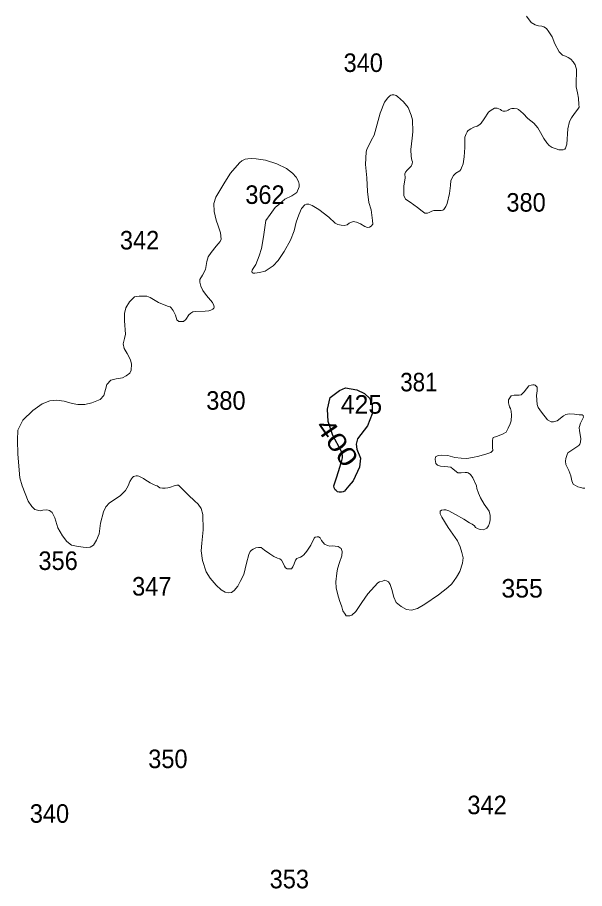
# Model space of a CAD drawing. Extents: x 445.4 to 500, y 8728.7 to 8784.
# Drawn here: x 453.47 to 458.36, y 8752.84 to 8760.36 of the extents above; entities that cross this region are included whole.
import ezdxf
from ezdxf.enums import TextEntityAlignment as Align

# ---------------------------------------------------------------- set-up
doc = ezdxf.new("R2010")
doc.units = 0
doc.header["$LTSCALE"] = 0.064
doc.layers.add('1', color=7, linetype='Continuous', lineweight=25)
doc.layers.add('2', color=7, linetype='Continuous', lineweight=13)
doc.layers.add('21', color=7, linetype='Continuous')
doc.layers.add('61', color=7, linetype='Continuous')

msp = doc.modelspace()

# ---------------------------------------------------------------- linework, layer by layer
at = {"layer": '1'}
msp.add_lwpolyline([(456.3024, 8756.2833), (456.2935, 8756.2721), (456.2812, 8756.2654), (456.2656, 8756.2632), (456.2478, 8756.2643), (456.2333, 8756.2677), (456.2221, 8756.2766), (456.2132, 8756.2844), (456.2031, 8756.3), (456.202, 8756.3168), (456.2269, 8756.3972), (456.2528, 8756.4782), (456.269, 8756.5365), (456.2755, 8756.5591), (456.2755, 8756.5786), (456.2626, 8756.6207), (456.1912, 8756.7534), (456.1523, 8756.8732), (456.1458, 8756.9801), (456.1685, 8757.0805), (456.2496, 8757.142), (456.3015, 8757.1647), (456.3988, 8757.1453), (456.4636, 8757.1161), (456.5123, 8757.0708), (456.5317, 8757.0157), (456.5317, 8756.938), (456.4896, 8756.8344), (456.4052, 8756.7243), (456.3923, 8756.6789), (456.3988, 8756.6336), (456.4312, 8756.5559), (456.4215, 8756.4782), (456.3663, 8756.3616), (456.3292, 8756.3168)], close=True, dxfattribs=at)
at = {"layer": '2'}
for points in [[(457.8603, 8760.3698), (457.9029, 8760.3157), (457.9349, 8760.2953), (457.966, 8760.2864), (457.9944, 8760.282), (458.0104, 8760.2776), (458.0326, 8760.2643), (458.0539, 8760.2341), (458.0832, 8760.1915), (458.1066, 8760.1306), (458.143, 8760.0605), (458.1723, 8760.0321), (458.1989, 8760.0233), (458.2194, 8760.0126), (458.2442, 8759.9975), (458.2638, 8759.9754), (458.2798, 8759.9487), (458.2878, 8759.931), (458.2931, 8759.9115), (458.294, 8759.8656), (458.2904, 8759.8213), (458.2887, 8759.7885), (458.2904, 8759.7601), (458.302, 8759.7069), (458.3108, 8759.661), (458.3135, 8759.6078), (458.3144, 8759.5839), (458.3055, 8759.567), (458.2744, 8759.5289), (458.2487, 8759.4934), (458.2336, 8759.4597), (458.218, 8759.3988), (458.2079, 8759.2659), (458.197, 8759.2319), (458.1909, 8759.2221), (458.1763, 8759.2161), (458.1587, 8759.2167), (458.1398, 8759.2179), (458.1185, 8759.224), (458.0833, 8759.2367), (458.0583, 8759.2537), (458.037, 8759.2774), (458.0109, 8759.3157), (457.9828, 8759.3665), (457.9585, 8759.4054), (457.9256, 8759.4479), (457.8743, 8759.486), (457.8335, 8759.5309), (457.794, 8759.5631), (457.78, 8759.571), (457.7551, 8759.574), (457.735, 8759.5722), (457.7234, 8759.5698), (457.7119, 8759.5655), (457.7046, 8759.5601), (457.693, 8759.5522), (457.6784, 8759.5491), (457.6608, 8759.5497), (457.6516, 8759.5528), (457.6456, 8759.5564), (457.6364, 8759.5631), (457.6243, 8759.5698), (457.6091, 8759.5746), (457.5945, 8759.5771), (457.5847, 8759.5753), (457.558, 8759.5589), (457.5352, 8759.5403), (457.4969, 8759.4838), (457.4713, 8759.4461), (457.4628, 8759.4376), (457.4506, 8759.4291), (457.4372, 8759.42), (457.4079, 8759.4111), (457.3817, 8759.3984), (457.3665, 8759.3892), (457.3568, 8759.3807), (457.3495, 8759.371), (457.3404, 8759.3552), (457.3349, 8759.34), (457.3294, 8759.3249), (457.33, 8759.2357), (457.3245, 8759.1549), (457.3142, 8759.0972), (457.3013, 8759.0622), (457.2952, 8759.0465), (457.2854, 8759.0355), (457.2526, 8759.0143), (457.2325, 8758.996), (457.21, 8758.9511), (457.2063, 8758.9093)], [(457.2063, 8758.9093), (457.1966, 8758.8394), (457.1784, 8758.7532), (457.1658, 8758.728), (457.1555, 8758.7104), (457.1476, 8758.7013), (457.1391, 8758.697), (457.1269, 8758.6934), (457.0935, 8758.694), (457.0624, 8758.6934), (457.0466, 8758.6873), (457.0235, 8758.6746), (457.0083, 8758.6697), (456.9961, 8758.6697), (456.9864, 8758.6709), (456.9627, 8758.6873), (456.9219, 8758.7183), (456.8574, 8758.7651), (456.8172, 8758.7923), (456.8038, 8758.8233), (456.8044, 8758.8494), (456.8038, 8758.9041), (456.8154, 8758.9762), (456.8136, 8759.009), (456.8184, 8759.0248), (456.8337, 8759.0418), (456.8665, 8759.0746), (456.8768, 8759.0965), (456.8787, 8759.1123), (456.8744, 8759.1281), (456.8683, 8759.1577), (456.8647, 8759.2185), (456.875, 8759.3163), (456.8829, 8759.3707), (456.8787, 8759.4758), (456.8682, 8759.517), (456.8402, 8759.582), (456.8007, 8759.6312), (456.7502, 8759.6774), (456.7393, 8759.6853), (456.7295, 8759.6895), (456.7168, 8759.6907), (456.7028, 8759.6901), (456.693, 8759.6883), (456.6833, 8759.681), (456.665, 8759.6658), (456.6381, 8759.6268), (456.6002, 8759.533), (456.5472, 8759.3428), (456.5225, 8759.2967), (456.4852, 8759.2189), (456.4779, 8759.198), (456.4737, 8759.089), (456.4852, 8758.9741), (456.4915, 8758.8577), (456.503, 8758.7624), (456.5227, 8758.699), (456.5343, 8758.6079), (456.536, 8758.5767), (456.5217, 8758.5576), (456.507, 8758.5492), (456.4902, 8758.5471), (456.4692, 8758.5544), (456.4304, 8758.5796), (456.3958, 8758.5932), (456.3685, 8758.5974), (456.3341, 8758.5833), (456.316, 8758.5701), (456.2887, 8758.5639), (456.2646, 8758.566), (456.2342, 8758.5722), (456.2121, 8758.5848), (456.157, 8758.6363), (456.0699, 8758.7012), (456.0143, 8758.7369), (455.985, 8758.7473), (455.965, 8758.7484), (455.9503, 8758.7421), (455.923, 8758.7117), (455.9, 8758.6551), (455.8747, 8758.5928), (455.8589, 8758.5183), (455.8261, 8758.4372), (455.7726, 8758.3408), (455.7211, 8758.2622), (455.6781, 8758.215), (455.6078, 8758.171), (455.5585, 8758.1574), (455.5186, 8758.1521), (455.505, 8758.1521), (455.4966, 8758.1584), (455.4934, 8758.1668), (455.4966, 8758.1794), (455.506, 8758.1941), (455.5291, 8758.2286), (455.5575, 8758.3009), (455.5783, 8758.3647), (455.5942, 8758.4653), (455.6146, 8758.6075), (455.6508, 8758.6595), (455.696, 8758.7182)], [(455.696, 8758.7182), (455.7254, 8758.7453), (455.7774, 8758.7904), (455.8384, 8758.8198), (455.8809, 8758.8487), (455.9026, 8758.8972), (455.9026, 8758.9214), (455.897, 8758.9426), (455.8766, 8758.9808), (455.8447, 8759.0153), (455.7923, 8759.0561), (455.708, 8759.0944), (455.6122, 8759.1275), (455.5317, 8759.139), (455.487, 8759.1429), (455.4589, 8759.1403), (455.4359, 8759.1352), (455.4065, 8759.1224), (455.3874, 8759.1046), (455.3106, 8759.0145), (455.2595, 8758.938), (455.1829, 8758.8078), (455.1663, 8758.753), (455.1701, 8758.6854), (455.1867, 8758.6104), (455.2045, 8758.5606), (455.2237, 8758.4994), (455.2301, 8758.4458), (455.2199, 8758.4267), (455.1867, 8758.3859), (455.1442, 8758.3316), (455.1161, 8758.2946), (455.1059, 8758.2525), (455.0931, 8758.1836), (455.0689, 8758.1351), (455.0459, 8758.0968), (455.0459, 8758.0739), (455.0548, 8758.0407), (455.0714, 8758.0037), (455.1035, 8757.9609), (455.1559, 8757.8997), (455.1648, 8757.8742), (455.1687, 8757.8602), (455.1661, 8757.8512), (455.1585, 8757.8423), (455.1393, 8757.8334), (455.1227, 8757.8283), (455.0908, 8757.8244), (455.009, 8757.8206), (454.986, 8757.8181), (454.9669, 8757.8066), (454.9493, 8757.7923), (454.9237, 8757.7528), (454.9033, 8757.7362), (454.8854, 8757.7349), (454.8649, 8757.7362), (454.8483, 8757.7489), (454.8343, 8757.7898), (454.8151, 8757.8319), (454.7972, 8757.8548), (454.7909, 8757.8612), (454.7653, 8757.8689), (454.69, 8757.9008), (454.6184, 8757.9441), (454.589, 8757.9543), (454.5584, 8757.9556), (454.5213, 8757.9556), (454.4817, 8757.948), (454.4651, 8757.9326), (454.4383, 8757.9059), (454.4064, 8757.8523), (454.3949, 8757.8051), (454.3962, 8757.7426), (454.4051, 8757.6252), (454.3952, 8757.5904), (454.3857, 8757.5431), (454.3928, 8757.5039), (454.4186, 8757.4596), (454.449, 8757.4058), (454.456, 8757.3685), (454.4536, 8757.3171), (454.4419, 8757.2914), (454.4115, 8757.2657), (454.3788, 8757.2493), (454.325, 8757.2423), (454.2782, 8757.2307), (454.2432, 8757.1933), (454.233, 8757.1499), (454.2167, 8757.0986), (454.1863, 8757.0635), (454.1138, 8757.0355), (454.0553, 8757.0191), (453.9945, 8757.0191), (453.9454, 8757.0285), (453.8752, 8757.0495), (453.8097, 8757.0565), (453.7512, 8757.0518), (453.6858, 8757.0261), (453.6062, 8756.9678), (453.5197, 8756.886), (453.4753, 8756.7996)], [(457.3587, 8756.4316), (457.3493, 8756.4332), (457.3337, 8756.4332), (457.2978, 8756.43), (457.2697, 8756.4316), (457.2291, 8756.4628), (457.2088, 8756.4784), (457.1823, 8756.4815), (457.1214, 8756.4877), (457.0949, 8756.4971), (457.0793, 8756.5096), (457.0761, 8756.5267), (457.073, 8756.5454), (457.0761, 8756.5672), (457.0996, 8756.5797), (457.1308, 8756.5828), (457.1823, 8756.5813), (457.2447, 8756.5626), (457.2994, 8756.5563), (457.3462, 8756.5548), (457.3962, 8756.5626), (457.4492, 8756.5735), (457.5195, 8756.5937), (457.5538, 8756.6062), (457.571, 8756.6234), (457.5694, 8756.6483), (457.5684, 8756.7083), (457.57, 8756.7255), (457.5747, 8756.7364), (457.6041, 8756.745), (457.6548, 8756.7646), (457.686, 8756.7824), (457.7029, 8756.8152), (457.7216, 8756.8526), (457.7287, 8756.8775), (457.7323, 8756.9273), (457.729, 8756.9635), (457.7245, 8756.984), (457.7138, 8757.0009), (457.7076, 8757.0338), (457.7067, 8757.0471), (457.7076, 8757.0613), (457.7174, 8757.0773), (457.7299, 8757.0942), (457.7563, 8757.0994), (457.7786, 8757.1011), (457.7975, 8757.1011), (457.8164, 8757.1045), (457.8422, 8757.1303), (457.8817, 8757.18), (457.9023, 8757.1852), (457.9161, 8757.1886), (457.9281, 8757.1886), (457.9367, 8757.1869), (457.9401, 8757.1835), (457.9522, 8757.1697), (457.9539, 8757.1371), (457.947, 8757.0977), (457.9539, 8757.0205), (457.9608, 8756.993), (457.99, 8756.9535), (458.0415, 8756.8883), (458.0742, 8756.8712), (458.0948, 8756.8695), (458.1257, 8756.8781), (458.1807, 8756.9209), (458.1996, 8756.933), (458.2305, 8756.9381), (458.2752, 8756.9364), (458.3164, 8756.9312), (458.3302, 8756.9312), (458.3405, 8756.9312), (458.3491, 8756.9261), (458.3508, 8756.9227), (458.3525, 8756.9107), (458.3267, 8756.8592), (458.3147, 8756.8214), (458.3171, 8756.7928), (458.3309, 8756.7259), (458.3274, 8756.695), (458.3206, 8756.6778), (458.312, 8756.6675), (458.269, 8756.6383), (458.2192, 8756.6023), (458.2123, 8756.5886), (458.202, 8756.5543), (458.1986, 8756.5302), (458.202, 8756.5028), (458.2278, 8756.4513), (458.245, 8756.4033), (458.2536, 8756.3604), (458.2639, 8756.3312), (458.3034, 8756.3089), (458.3309, 8756.3038), (458.3463, 8756.2969), (458.3652, 8756.2969)], [(453.4753, 8756.7996), (453.4729, 8756.7108), (453.4754, 8756.5904), (453.4941, 8756.3872), (453.5127, 8756.3168), (453.5396, 8756.2515), (453.5665, 8756.1854), (453.5975, 8756.1399), (453.6224, 8756.1151), (453.6451, 8756.1069), (453.67, 8756.1027), (453.6927, 8756.1089), (453.7259, 8756.111), (453.7486, 8756.1048), (453.7735, 8756.0883), (453.7942, 8756.0408), (453.8211, 8755.9561), (453.8604, 8755.8858), (453.9002, 8755.839), (453.9395, 8755.806), (453.9829, 8755.7977), (454.0388, 8755.7894), (454.0678, 8755.7874), (454.0989, 8755.7894), (454.1299, 8755.806), (454.1547, 8755.8493), (454.1775, 8755.9051), (454.1899, 8755.996), (454.2152, 8756.0944), (454.2359, 8756.1378), (454.267, 8756.1709), (454.3146, 8756.2039), (454.3601, 8756.2349), (454.4036, 8756.2783), (454.4266, 8756.3168), (454.4419, 8756.3546), (454.4556, 8756.3775), (454.4635, 8756.3897), (454.4743, 8756.3976), (454.4836, 8756.4005), (454.4966, 8756.4048), (454.5074, 8756.4055), (454.5189, 8756.4012), (454.5361, 8756.3926), (454.5584, 8756.3818), (454.5721, 8756.3718), (454.6181, 8756.3452), (454.6511, 8756.3259), (454.667, 8756.3208), (454.6777, 8756.3168), (454.7005, 8756.3011), (454.7233, 8756.299), (454.746, 8756.299), (454.7688, 8756.3011), (454.7936, 8756.3073), (454.8247, 8756.3168), (454.8352, 8756.3215), (454.8474, 8756.3237), (454.856, 8756.3244), (454.8611, 8756.323), (454.8682, 8756.3168), (454.9489, 8756.2371), (454.9985, 8756.1896), (455.0317, 8756.1606), (455.0565, 8756.1214), (455.071, 8756.0697), (455.0731, 8755.9375), (455.0627, 8755.8247), (455.0565, 8755.7566), (455.0689, 8755.6739), (455.1, 8755.5768), (455.1331, 8755.521), (455.1854, 8755.4621), (455.2288, 8755.4208), (455.264, 8755.4001), (455.2888, 8755.396), (455.3178, 8755.3981), (455.3427, 8755.4166), (455.3716, 8755.4538), (455.3944, 8755.4931), (455.4234, 8755.553), (455.4482, 8755.6501), (455.467, 8755.7255), (455.4794, 8755.7523), (455.4918, 8755.7627), (455.5063, 8755.773), (455.527, 8755.7833), (455.5498, 8755.7875), (455.5746, 8755.7854), (455.6036, 8755.7627), (455.6491, 8755.7317), (455.6823, 8755.7089), (455.7154, 8755.6945), (455.7361, 8755.6883), (455.7485, 8755.678), (455.7692, 8755.6408), (455.7754, 8755.6263), (455.7837, 8755.6098), (455.7982, 8755.6036), (455.8127, 8755.6015), (455.8354, 8755.6036)], [(455.8354, 8755.6036), (455.8458, 8755.6181), (455.8582, 8755.6449), (455.8706, 8755.6759), (455.881, 8755.6904), (455.8955, 8755.6966), (455.912, 8755.7028), (455.9265, 8755.711), (455.941, 8755.7234), (455.9679, 8755.7544), (456.001, 8755.806), (456.03, 8755.866), (456.0383, 8755.8742), (456.0569, 8755.8783), (456.0693, 8755.8783), (456.0838, 8755.8701), (456.0942, 8755.8453), (456.1211, 8755.8143), (456.1459, 8755.804), (456.1666, 8755.7978), (456.1894, 8755.7998), (456.2121, 8755.7978), (456.239, 8755.7936), (456.2645, 8755.777), (456.2728, 8755.7522), (456.2687, 8755.713), (456.2501, 8755.6572), (456.2314, 8755.6014), (456.2252, 8755.5663), (456.219, 8755.4899), (456.2213, 8755.4392), (456.2337, 8755.3793), (456.2482, 8755.3297), (456.2689, 8755.2739), (456.2793, 8755.2388), (456.2979, 8755.2099), (456.3082, 8755.1975), (456.3269, 8755.1954), (456.3393, 8755.1954), (456.3558, 8755.2016), (456.391, 8755.2347), (456.4428, 8755.3111), (456.4945, 8755.3855), (456.5794, 8755.4805), (456.5939, 8755.4909), (456.6208, 8755.4971), (456.6415, 8755.5033), (456.6539, 8755.4991), (456.6705, 8755.4888), (456.6849, 8755.4681), (456.7015, 8755.4247), (456.7181, 8755.3586), (456.7388, 8755.3132), (456.7802, 8755.2781), (456.8257, 8755.2512), (456.8692, 8755.245), (456.9209, 8755.2595), (456.9851, 8755.2967), (457.1021, 8755.3792), (457.1828, 8755.4412), (457.218, 8755.4743), (457.2594, 8755.5301), (457.2863, 8755.5796), (457.3112, 8755.6499), (457.3154, 8755.6985), (457.305, 8755.7439), (457.2905, 8755.7914), (457.2657, 8755.8431), (457.185, 8755.9588), (457.1311, 8756.0467), (457.1166, 8756.0777), (457.1187, 8756.0984), (457.129, 8756.1087), (457.1477, 8756.1108), (457.1663, 8756.1108), (457.1911, 8756.1025), (457.2491, 8756.0695), (457.3215, 8756.0302), (457.3712, 8755.9992), (457.394, 8755.9868), (457.4126, 8755.9724), (457.4229, 8755.96), (457.4436, 8755.9476), (457.4623, 8755.9414), (457.4871, 8755.9393), (457.5037, 8755.9435), (457.5182, 8755.9517), (457.5326, 8755.9744), (457.543, 8755.9972), (457.5471, 8756.024), (457.5492, 8756.0426), (457.5471, 8756.0612), (457.5389, 8756.0984), (457.4975, 8756.1604), (457.4643, 8756.2141), (457.4478, 8756.2554), (457.4333, 8756.2947), (457.4292, 8756.3168), (457.3993, 8756.3864), (457.379, 8756.416), (457.3587, 8756.4316)]]:
    msp.add_lwpolyline(points, dxfattribs=at)

# ---------------------------------------------------------------- texts
at = {"layer": '21'}
for s, width, p in [('340', 0.95, (456.2845, 8759.8883)), ('362', 0.95, (455.4376, 8758.75)), ('380', 0.95, (457.6882, 8758.6833)), ('342', 0.95, (454.3562, 8758.3571)), ('381', 0.9, (456.7731, 8757.1332)), ('380', 0.95, (455.1007, 8756.9746)), ('356', 0.95, (453.6541, 8755.5924)), ('347', 0.95, (454.4614, 8755.3716)), ('350', 0.95, (454.6004, 8753.8832)), ('342', 0.95, (457.352, 8753.4858)), ('340', 0.95, (453.5795, 8753.4117)), ('353', 0.95, (455.6472, 8752.8464))]:
    msp.add_text(s, height=0.16, dxfattribs=dict(at, width=width)).set_placement(p)
for s, p in [('425', (456.2603, 8756.9406)), ('355', (457.6456, 8755.3544))]:
    msp.add_text(s, height=0.16, dxfattribs=at).set_placement(p)
at = {"layer": '61', "width": 1.25}
msp.add_text('400', height=0.16, rotation=304.864, dxfattribs=at).set_placement((456.1635, 8756.6471), align=Align.CENTER)

doc.saveas('drawing.dxf')
